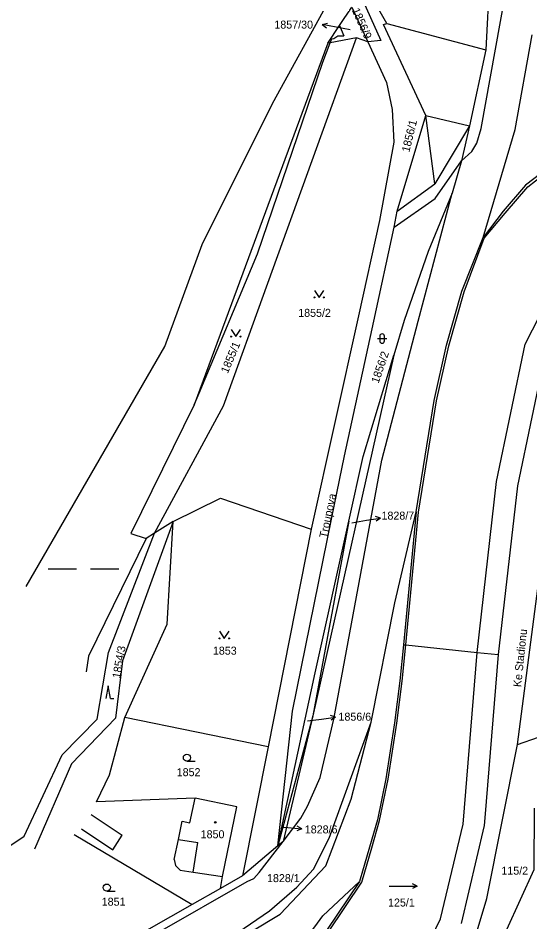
# Model space of a CAD drawing. Extents: x -783716 to -783033, y -1065203 to -1064697.
# Drawn here: x -783577.2 to -783468.4, y -1065075 to -1064883 of the extents above; entities that cross this region are included whole.
import ezdxf

# ---------------------------------------------------------------- set-up
doc = ezdxf.new("R2010")
doc.units = 0
for name, color, linetype in [('Budovy', 7, 'Continuous'), ('Doplňkové značky', 7, 'Continuous'), ('Doplňující texty', 7, 'Continuous'), ('Kultury', 7, 'Continuous'), ('Stromy_porost', 7, 'Continuous'), ('Značky IS', 7, 'Continuous')]:
    doc.layers.add(name, color=color, linetype=linetype)

msp = doc.modelspace()

# ---------------------------------------------------------------- linework, layer by layer
at = {"layer": 'Budovy'}
for p, q in [((-783523.1, -1064901.15), (-783508.82, -1064875.14)), ((-783506.26, -1064880.64), (-783502.83, -1064888)), ((-783502.83, -1064888), (-783505.26, -1064887.15)), ((-783495.09, -1064947.27), (-783497.32, -1064954.63)), ((-783497.32, -1064954.63), (-783514.53, -1065031.25)), ((-783503.85, -1064976.14), (-783497.32, -1064954.63)), ((-783506.88, -1064989.89), (-783503.85, -1064976.14)), ((-783544.22, -1064989.94), (-783548.17, -1064992.43)), ((-783506.88, -1064989.89), (-783514.53, -1065031.25)), ((-783514.84, -1064991.54), (-783524.01, -1065037.82)), ((-783548.17, -1064992.43), (-783549.97, -1064993.56)), ((-783524.01, -1065037.82), (-783554.46, -1065031.61)), ((-783514.53, -1065031.25), (-783521.94, -1065058.84)), ((-783471.02, -1065037.32), (-783466.55, -1065035.74)), ((-783524.01, -1065037.82), (-783529.45, -1065065.23)), ((-783565.28, -1065056.42), (-783540.15, -1065071.29)), ((-783521.94, -1065058.84), (-783529.45, -1065065.23)), ((-783529.45, -1065065.23), (-783534.17, -1065067.9)), ((-783534.17, -1065067.9), (-783540.15, -1065071.29)), ((-783540.15, -1065071.29), (-783559.84, -1065082.45))]:
    msp.add_line(p, q, dxfattribs=at)
for points in [[(-783476.38, -1064865.8), (-783476.96, -1064874.51), (-783477.75, -1064889.71), (-783481.18, -1064905.88)], [(-783490.48, -1064903.67), (-783499.51, -1064884.38), (-783498.76, -1064884.16), (-783503.56, -1064875.78)], [(-783504.45, -1064877.9), (-783500.04, -1064887.77), (-783502.83, -1064888)], [(-783586.68, -1065149.16), (-783564.78, -1065139.29), (-783532.97, -1065123.26), (-783520.29, -1065114.03), (-783502.16, -1065097.24), (-783498.48, -1065093.26), (-783495.21, -1065089.71), (-783494.31, -1065088.74), (-783487.35, -1065074.33), (-783482.56, -1065054.25), (-783479.58, -1065017.78), (-783475.47, -1064981.45), (-783469.34, -1064952.28), (-783461.55, -1064937.01), (-783445.96, -1064920.48), (-783433.11, -1064911.15), (-783418.04, -1064903.77), (-783403.59, -1064898.67), (-783393.97, -1064894.19), (-783364.93, -1064886.92), (-783332.97, -1064881.2)], [(-783511.32, -1064888.33), (-783508.83, -1064884.54), (-783506.26, -1064880.64)], [(-783402.29, -1064881.78), (-783407.72, -1064883.89), (-783423.7, -1064890.15), (-783437.08, -1064895.97), (-783447.3, -1064901.74), (-783469.27, -1064918.46), (-783474.07, -1064924.03), (-783478.28, -1064929.62)], [(-783548.17, -1064992.43), (-783533.48, -1064965.38), (-783505.26, -1064887.15)], [(-783502.83, -1064888), (-783498.87, -1064896.64), (-783497.64, -1064902.39), (-783497.32, -1064909.38), (-783500.31, -1064925.98), (-783504.81, -1064946.28), (-783514.84, -1064991.54)], [(-783505.26, -1064887.15), (-783510.81, -1064888.23), (-783511.32, -1064888.33)], [(-783478.28, -1064929.62), (-783471.49, -1064906.69), (-783467.9, -1064886.57)], [(-783511.32, -1064888.33), (-783539.74, -1064965.15), (-783553.24, -1064992.51), (-783549.97, -1064993.56)], [(-783575.44, -1065003.73), (-783545.98, -1064952.75), (-783538.04, -1064931.1), (-783523.1, -1064901.15)], [(-783521.94, -1065058.84), (-783518.81, -1065030.21), (-783510.48, -1064989.06), (-783507.81, -1064976.02), (-783501.56, -1064947.4), (-783497.23, -1064927.39), (-783496.57, -1064924.02), (-783490.48, -1064903.67)], [(-783481.18, -1064905.88), (-783488.59, -1064918.22), (-783490.48, -1064903.67)], [(-783481.18, -1064905.88), (-783482.9, -1064913.3), (-783484.87, -1064920.18), (-783490, -1064932.55), (-783495.09, -1064947.27)], [(-783416.55, -1064908), (-783430.48, -1064914.8), (-783443.35, -1064924.13), (-783457.58, -1064939.04), (-783464.9, -1064953.22), (-783471.03, -1064982.39), (-783475.1, -1065018.21), (-783477.98, -1065052.91), (-783478.07, -1065054.51), (-783482.97, -1065075.36)], [(-783492.53, -1064987.86), (-783488.71, -1064964.21), (-783486.09, -1064952.5), (-783482.83, -1064940.99), (-783478.28, -1064929.62)], [(-783471.02, -1065037.32), (-783462.59, -1064972.66), (-783456.33, -1064954.34)], [(-783544.22, -1064989.94), (-783534.18, -1064984.98), (-783514.84, -1064991.54)], [(-783607.85, -1065123.43), (-783546.39, -1065088.37), (-783521.44, -1065073.34), (-783511.77, -1065063.08), (-783506.35, -1065048.95), (-783502.14, -1065032.55), (-783497.09, -1065007.24), (-783492.53, -1064987.86)], [(-783492.53, -1064987.86), (-783495.21, -1065016.12), (-783496.04, -1065023.77), (-783497.17, -1065032.71), (-783499.02, -1065044.63), (-783500.79, -1065053.34), (-783502.44, -1065059.14), (-783504.59, -1065066.42)], [(-783544.22, -1064989.94), (-783555.01, -1065019.55), (-783556.5, -1065031.75), (-783565.81, -1065041.46), (-783573.68, -1065059.58)], [(-783554.46, -1065031.61), (-783545.48, -1065011.72), (-783544.22, -1064989.94)], [(-783521.94, -1065058.84), (-783514.02, -1065022.07), (-783506.88, -1064989.89)], [(-783583.27, -1065061.66), (-783575.9, -1065056.8), (-783567.79, -1065039.53), (-783560.38, -1065031.94), (-783557.99, -1065017.77), (-783548.17, -1064992.43)], [(-783549.97, -1064993.56), (-783562.19, -1065018.56), (-783562.68, -1065021.88)], [(-783560.55, -1065049.48), (-783557.75, -1065043.78), (-783554.46, -1065031.61)], [(-783514.53, -1065031.25), (-783520.86, -1065057.92), (-783521.94, -1065058.84)], [(-783484.32, -1065092.79), (-783477.5, -1065070.05), (-783471.02, -1065037.32)], [(-783534.17, -1065067.9), (-783533.71, -1065065.39), (-783530.68, -1065050.59), (-783539.56, -1065048.72), (-783560.55, -1065049.48)], [(-783467.47, -1065050.82), (-783467.56, -1065063.94), (-783473.33, -1065076.72), (-783484.32, -1065092.79)], [(-783504.59, -1065066.42), (-783511.59, -1065076.83), (-783514.83, -1065080.59), (-783529.78, -1065097.96), (-783559.97, -1065115.54), (-783579.36, -1065123.41), (-783592.85, -1065128.61), (-783597.17, -1065129.64), (-783598.62, -1065130.29), (-783638.54, -1065148.19)], [(-783580.95, -1065119.21), (-783561.96, -1065112.08), (-783531.67, -1065094.68), (-783516.49, -1065079.31), (-783513.55, -1065075.3), (-783512.37, -1065073.74), (-783504.59, -1065066.42)]]:
    msp.add_lwpolyline(points, dxfattribs=at)
at = {"layer": 'Doplňkové značky'}
for p, q in [((-783478.7, -1064906.42), (-783472.96, -1064874.3)), ((-783498.76, -1064884.16), (-783477.75, -1064889.71)), ((-783508.83, -1064884.54), (-783507.96, -1064886.77)), ((-783512.4, -1064892.33), (-783510.81, -1064888.23)), ((-783510.81, -1064888.23), (-783510.48, -1064887.37)), ((-783510.48, -1064887.37), (-783510.03, -1064887.32)), ((-783510.03, -1064887.32), (-783509.23, -1064886.74)), ((-783509.23, -1064886.74), (-783507.96, -1064886.77)), ((-783526.3, -1064933.08), (-783512.4, -1064892.33)), ((-783490.48, -1064903.67), (-783481.18, -1064905.88)), ((-783479.66, -1064909.59), (-783478.7, -1064906.42)), ((-783482.9, -1064913.3), (-783480.72, -1064911.3)), ((-783480.72, -1064911.3), (-783479.66, -1064909.59)), ((-783468.82, -1064918.84), (-783457.08, -1064909.54)), ((-783488.53, -1064921.33), (-783482.9, -1064913.3)), ((-783496.57, -1064924.02), (-783488.59, -1064918.22)), ((-783473.62, -1064924.41), (-783468.82, -1064918.84)), ((-783492.09, -1064947.38), (-783484.87, -1064920.18)), ((-783497.23, -1064927.39), (-783488.53, -1064921.33)), ((-783478.12, -1064929.74), (-783473.62, -1064924.41)), ((-783482.35, -1064941.13), (-783478.12, -1064929.74)), ((-783538.68, -1064962.67), (-783526.3, -1064933.08)), ((-783485.61, -1064952.64), (-783482.35, -1064941.13)), ((-783499.88, -1064976.88), (-783492.09, -1064947.38)), ((-783488.22, -1064964.29), (-783485.61, -1064952.64)), ((-783539.74, -1064965.15), (-783538.68, -1064962.67)), ((-783492.04, -1064987.94), (-783488.22, -1064964.29)), ((-783510.06, -1065031.92), (-783499.88, -1064976.88)), ((-783494.72, -1065016.18), (-783492.04, -1064987.94)), ((-783495.55, -1065023.83), (-783494.72, -1065016.18)), ((-783495.21, -1065016.12), (-783494.72, -1065016.18)), ((-783494.72, -1065016.18), (-783479.58, -1065017.78)), ((-783479.58, -1065017.78), (-783475.1, -1065018.21)), ((-783496.68, -1065032.79), (-783495.55, -1065023.83)), ((-783512.95, -1065044.33), (-783510.06, -1065031.92)), ((-783511.02, -1065057.21), (-783502.14, -1065032.55)), ((-783498.53, -1065044.71), (-783496.68, -1065032.79)), ((-783515.67, -1065050.42), (-783512.95, -1065044.33)), ((-783500.31, -1065053.48), (-783498.53, -1065044.71)), ((-783540.69, -1065053.93), (-783539.56, -1065048.72)), ((-783517.07, -1065052.97), (-783515.67, -1065050.42)), ((-783561.64, -1065052.19), (-783555.05, -1065056.6)), ((-783520.86, -1065057.92), (-783517.07, -1065052.97)), ((-783563.68, -1065055.24), (-783557.06, -1065059.69)), ((-783543.11, -1065057.52), (-783542.3, -1065053.59)), ((-783542.3, -1065053.59), (-783540.69, -1065053.93)), ((-783501.96, -1065059.28), (-783500.31, -1065053.48)), ((-783557.06, -1065059.69), (-783555.05, -1065056.6)), ((-783514.35, -1065063.8), (-783511.02, -1065057.21)), ((-783543.99, -1065061.77), (-783543.11, -1065057.52)), ((-783543.11, -1065057.52), (-783539, -1065058.14)), ((-783539.97, -1065064.43), (-783539, -1065058.14)), ((-783525.91, -1065064.52), (-783520.86, -1065057.92)), ((-783504.11, -1065066.56), (-783501.96, -1065059.28)), ((-783543.99, -1065061.77), (-783543.72, -1065063.05)), ((-783543.72, -1065063.05), (-783542.74, -1065064.02)), ((-783542.74, -1065064.02), (-783539.97, -1065064.43)), ((-783539.97, -1065064.43), (-783533.71, -1065065.39)), ((-783527.07, -1065065.81), (-783525.91, -1065064.52)), ((-783517.95, -1065067.64), (-783514.35, -1065063.8)), ((-783547.52, -1065077.32), (-783528.48, -1065066.44)), ((-783528.48, -1065066.44), (-783527.07, -1065065.81)), ((-783511.17, -1065077.1), (-783504.11, -1065066.56)), ((-783523.72, -1065072.69), (-783517.95, -1065067.64)), ((-783530.49, -1065077.27), (-783523.72, -1065072.69))]:
    msp.add_line(p, q, dxfattribs=at)
at = {"layer": 'Doplňující texty'}
msp.add_circle((-783535.26, -1065053.86), 0.175, dxfattribs=at)
at = {"layer": 'Kultury'}
for p, q in [((-783500.79, -1064951.08), (-783498.79, -1064951.08)), ((-783500.29, -1064950.58), (-783500.29, -1064951.58)), ((-783499.29, -1064951.58), (-783499.29, -1064950.58)), ((-783570.77, -1064999.97), (-783564.77, -1064999.97)), ((-783561.77, -1064999.97), (-783555.77, -1064999.97)), ((-783558.02, -1065024.87), (-783558.52, -1065027.55)), ((-783557.52, -1065027.55), (-783558.02, -1065024.87)), ((-783557.52, -1065027.55), (-783556.85, -1065027.55)), ((-783541.3, -1065040.87), (-783539.55, -1065040.87)), ((-783558.32, -1065068.47), (-783556.57, -1065068.47)), ((-783498.32, -1065067.39), (-783492.32, -1065067.39)), ((-783492.32, -1065067.39), (-783493.3, -1065066.89)), ((-783492.32, -1065067.39), (-783493.3, -1065067.89))]:
    msp.add_line(p, q, dxfattribs=at)
for points in [[(-783514.19, -1064940.83), (-783513.19, -1064942.33), (-783512.19, -1064940.83)], [(-783531.89, -1064949.17), (-783530.89, -1064950.67), (-783529.89, -1064949.17)], [(-783534.34, -1065013.27), (-783533.34, -1065014.77), (-783532.34, -1065013.27)]]:
    msp.add_lwpolyline(points, dxfattribs=at)
for centre, radius in [((-783514.19, -1064942.33), 0.1), ((-783512.19, -1064942.33), 0.1), ((-783531.89, -1064950.67), 0.1), ((-783529.89, -1064950.67), 0.1), ((-783534.34, -1065014.77), 0.1), ((-783532.34, -1065014.77), 0.1), ((-783541.3, -1065040.12), 0.75), ((-783558.32, -1065067.72), 0.75)]:
    msp.add_circle(centre, radius, dxfattribs=at)
for centre, start, end in [((-783499.79, -1064950.58), 0, 180), ((-783499.79, -1064951.58), 180, 359.9879)]:
    msp.add_arc(centre, 0.5, start, end, dxfattribs=at)
at = {"layer": 'Stromy_porost'}
for p, q in [((-783512.51, -1064884.35), (-783511.43, -1064884.05)), ((-783509.56, -1064884.92), (-783512.51, -1064884.35)), ((-783512.51, -1064884.35), (-783511.62, -1064885.03)), ((-783506.56, -1064885.49), (-783509.56, -1064884.92)), ((-783506.2, -1064990.21), (-783503.11, -1064989.69)), ((-783503.11, -1064989.69), (-783500.15, -1064989.22)), ((-783500.15, -1064989.22), (-783501.21, -1064988.88)), ((-783500.15, -1064989.22), (-783501.06, -1064989.87)), ((-783515.64, -1065032.28), (-783512.68, -1065031.91)), ((-783512.68, -1065031.91), (-783509.7, -1065031.54)), ((-783509.7, -1065031.54), (-783510.76, -1065031.17)), ((-783509.7, -1065031.54), (-783510.63, -1065032.16)), ((-783520.65, -1065054.88), (-783519.86, -1065054.96)), ((-783519.86, -1065054.96), (-783516.87, -1065055.22)), ((-783516.87, -1065055.22), (-783517.91, -1065055.63)), ((-783516.87, -1065055.22), (-783517.82, -1065054.64))]:
    msp.add_line(p, q, dxfattribs=at)

# ---------------------------------------------------------------- texts
for s, rotation, p in [('Troupova', 78, (-783511.52, -1064993.58)), ('Ke Stadionu', 84, (-783470.24, -1065025.19))]:
    msp.add_text(s, height=1.7, rotation=rotation, dxfattribs=at).set_placement(p)
at = {"layer": 'Značky IS'}
for s, rotation, p in [('1856/9', 294, (-783506.27, -1064881.28)), ('1856/1', 76, (-783494.02, -1064911.6)), ('1855/1', 67, (-783532.61, -1064958.61)), ('1856/2', 71, (-783500.56, -1064960.72)), ('1854/3', 80, (-783555.5, -1065023.37))]:
    msp.add_text(s, height=1.7, rotation=rotation, dxfattribs=at).set_placement(p)
for s, p in [('1857/30', (-783522.7, -1064885.22)), ('1855/2', (-783517.63, -1064946.46)), ('1828/7', (-783499.92, -1064989.54)), ('1853', (-783535.77, -1065018.23)), ('1856/6', (-783509.07, -1065032.26)), ('1852', (-783543.46, -1065044.05)), ('1828/6', (-783516.23, -1065056.21)), ('1850', (-783538.37, -1065057.24)), ('1828/1', (-783524.26, -1065066.56)), ('115/2', (-783474.43, -1065064.97)), ('1851', (-783559.41, -1065071.57)), ('125/1', (-783498.53, -1065071.74))]:
    msp.add_text(s, height=1.7, dxfattribs=at).set_placement(p)

doc.saveas('drawing.dxf')
